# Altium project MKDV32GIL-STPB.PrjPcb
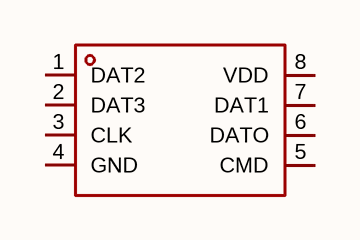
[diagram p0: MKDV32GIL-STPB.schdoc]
1 sheet, 1 parts. Net scope: global (net labels, ports and power ports of the same name join across sheets).

## Sheet MKDV32GIL-STPB.schdoc
size 127 x 101 mm

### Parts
U?  mkdv32gil-stpb  [LGA-8_L8.0-W6.6-P1.27-TL-MKDV32GIL-STPB]  (value not drawn)

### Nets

Not connected (* = marked no-connect by the designer): U? 1(DAT2) 2(DAT3) 3(CLK) 4(GND) 5(CMD) 6(DATO) 7(DAT1) 8(VDD)

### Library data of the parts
U? = mkdv32gil-stpb: 存储容量:32Gbit;时钟频率(fc):50MHz;工作电压:2.7V~3.6V;; Manufacturer: MK(米客方德); AddInBom: yes; Memory Size: 32Gbit; Interface: SPI; Clock Frequency: 50MHz; Standby Supply Current: 250uA; Program / Erase Cycles: 3万次; ECC: 有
